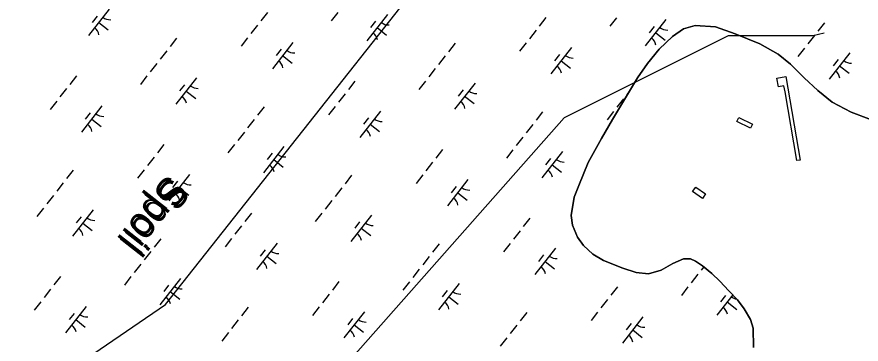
# Model space of a CAD drawing. Extents: x 3896831 to 3918110, y 171006 to 193349.
# Drawn here: x 3911925 to 3913188, y 183055 to 183545 of the extents above; entities that cross this region are included whole.
import ezdxf

# ---------------------------------------------------------------- set-up
doc = ezdxf.new("R2010")
doc.units = 0
for name, color, linetype in [('V-CHAN-DOCK', 7, 'Continuous'), ('V-CHAN-SPOL', 7, 'Continuous'), ('V-TOPO-SHOR', 7, 'Continuous'), ('V-UTIL-LINE', 7, 'Continuous'), ('V-WETL-SWMP', 7, 'Continuous')]:
    doc.layers.add(name, color=color, linetype=linetype)

msp = doc.modelspace()

# ---------------------------------------------------------------- linework, layer by layer
at = {"layer": 'V-CHAN-DOCK'}
for points in [[(3913092.1, 183329.6), (3913074.7, 183432.5), (3913073.1, 183441.5), (3913064.8, 183440.1), (3913062.6, 183453.1), (3913075.9, 183455.3), (3913097.1, 183330.5)], [(3913005.6, 183394.1), (3913025.8, 183384), (3913022.9, 183378.1), (3913002.6, 183388.2)], [(3912941, 183290), (3912955.8, 183279.8), (3912951.1, 183273), (3912936.4, 183283.2)]]:
    msp.add_lwpolyline(points, close=True, dxfattribs=at)
at = {"layer": 'V-TOPO-SHOR'}
msp.add_lwpolyline([(3913027.4, 183050.2), (3913027.2, 183079.1), (3913023, 183091.9), (3913013.7, 183107.9), (3913003.4, 183121.4), (3912990.4, 183134.8), (3912977.1, 183149), (3912964.9, 183160.6), (3912951.3, 183172.2), (3912940.6, 183179.4), (3912933.2, 183182.7), (3912922.6, 183182.6), (3912906.9, 183175.5), (3912889.4, 183165.8), (3912870.4, 183160.1), (3912852.1, 183162.2), (3912832.2, 183168.6), (3912802.8, 183180.4), (3912787.3, 183189.8), (3912773.3, 183202.5), (3912764, 183214.9), (3912756.9, 183232.8), (3912754.6, 183247.4), (3912759.1, 183274.9), (3912765.9, 183292.6), (3912780.3, 183326.8), (3912800.1, 183362.8), (3912816.7, 183391.2), (3912839.1, 183428.4), (3912853.9, 183453.4), (3912868.7, 183474.8), (3912886.5, 183496.2), (3912906.1, 183515.4), (3912922.5, 183526.9), (3912940.4, 183531.8), (3912970.8, 183529.5), (3913000.2, 183519.2), (3913037, 183504.5), (3913064.6, 183489), (3913083, 183473.8), (3913103.4, 183453.4), (3913123.7, 183434.5), (3913145.4, 183417.2), (3913173.8, 183402), (3913200.2, 183392)], dxfattribs=at)
at = {"layer": 'V-UTIL-LINE'}
for points in [[(3905549.4, 173652.6), (3906763.3, 174938.4), (3906949.5, 175133), (3906970.6, 175166.8), (3907325.9, 175860.5), (3907748.9, 176681), (3908142.2, 177273.2), (3908679.4, 178098), (3908869.7, 178381.4), (3908937.4, 178537.8), (3909170, 179117.3), (3909533.8, 179633.3), (3910092.1, 180424.3), (3910333.2, 180766.9), (3910760.4, 181291.4), (3910921.1, 181524), (3911225.6, 181951.2), (3911822, 182788.6), (3911961.6, 182987.4), (3912147.7, 183114.3), (3912722.9, 183841.8), (3913090.9, 184307.1), (3913848, 185258.8), (3914364, 185910.1)], [(3913133.2, 183520.4), (3913116.3, 183516.1), (3912989.4, 183516.1), (3912744.1, 183393.5), (3911902.4, 182441.8), (3910866.1, 181249.1), (3910603.9, 180953), (3910214.7, 180504.6), (3910138.6, 180390.4), (3909757.9, 179819.4), (3909457.6, 179366.9), (3909009.3, 178685.9), (3908785.1, 178351.7), (3908150.7, 177400.1), (3907770, 176816.4), (3907693.9, 176706.4), (3907647.3, 176630.3), (3907300.5, 175936.6), (3907025.6, 175369.8), (3906945.2, 175204.9), (3906416.5, 174650.8), (3905507.1, 173682.2)]]:
    msp.add_lwpolyline(points, dxfattribs=at)
at = {"layer": 'V-WETL-SWMP'}
for p, q in [((3912063.2, 183556), (3912032.3, 183516.7)), ((3912045.4, 183545.8), (3912038, 183536.4)), ((3912300.2, 183551.2), (3912290.4, 183538.6)), ((3912405.7, 183551.1), (3912395.8, 183538.5)), ((3912479.8, 183548.3), (3912449, 183509)), ((3912716.9, 183543.5), (3912707, 183530.9)), ((3912822.3, 183543.4), (3912812.5, 183530.8)), ((3912047.8, 183536.3), (3912061.9, 183525.2)), ((3912285.4, 183532.3), (3912275.6, 183519.7)), ((3912462, 183538.1), (3912454.6, 183528.7)), ((3912464.4, 183528.6), (3912478.6, 183517.5)), ((3912896.5, 183540.6), (3912865.6, 183501.3)), ((3912878.7, 183530.4), (3912871.3, 183521)), ((3912940.4, 183531.8), (3912922.5, 183526.9)), ((3912970.8, 183529.5), (3912940.4, 183531.8)), ((3913000.2, 183519.2), (3912970.8, 183529.5)), ((3913133.5, 183535.8), (3913123.7, 183523.2)), ((3912702.1, 183524.6), (3912692.2, 183512)), ((3912881.1, 183520.9), (3912895.2, 183509.8)), ((3912922.5, 183526.9), (3912906.1, 183515.4)), ((3913037, 183504.5), (3913000.2, 183519.2)), ((3913118.7, 183516.9), (3913108.8, 183504.3)), ((3912164.4, 183512.8), (3912154.5, 183500.2)), ((3912270.6, 183513.4), (3912260.8, 183500.8)), ((3912338.4, 183506.4), (3912307.6, 183467)), ((3912581, 183505.1), (3912571.2, 183492.5)), ((3912687.3, 183505.7), (3912677.4, 183493.1)), ((3912906.1, 183515.4), (3912886.5, 183496.2)), ((3913064.6, 183489), (3913037, 183504.5)), ((3912149.6, 183493.9), (3912139.7, 183481.3)), ((3912320.7, 183496.2), (3912313.2, 183486.7)), ((3912755.1, 183498.7), (3912724.2, 183459.3)), ((3912886.5, 183496.2), (3912868.7, 183474.8)), ((3913103.9, 183498), (3913094, 183485.4)), ((3913171.7, 183491), (3913140.9, 183451.6)), ((3912323, 183486.7), (3912337.2, 183475.6)), ((3912566.2, 183486.2), (3912556.4, 183473.6)), ((3912737.3, 183488.5), (3912729.9, 183479)), ((3912739.7, 183479), (3912753.8, 183467.9)), ((3913083, 183473.8), (3913064.6, 183489)), ((3913153.9, 183480.8), (3913146.5, 183471.3)), ((3912134.8, 183475), (3912124.9, 183462.4)), ((3912551.4, 183467.3), (3912541.6, 183454.7)), ((3912868.7, 183474.8), (3912853.9, 183453.4)), ((3913103.4, 183453.4), (3913083, 183473.8)), ((3913156.3, 183471.3), (3913170.5, 183460.2)), ((3912014.5, 183456.3), (3912004.6, 183443.7)), ((3912120, 183456.2), (3912110.1, 183443.6)), ((3912194.1, 183453.4), (3912163.3, 183414.1)), ((3912853.9, 183453.4), (3912839.1, 183428.4)), ((3913123.7, 183434.5), (3913103.4, 183453.4)), ((3912176.3, 183443.2), (3912168.9, 183433.8)), ((3912431.2, 183448.6), (3912421.3, 183436)), ((3912536.6, 183448.5), (3912526.7, 183435.9)), ((3912610.8, 183445.7), (3912579.9, 183406.4)), ((3911999.7, 183437.4), (3911989.8, 183424.8)), ((3912178.7, 183433.7), (3912192.9, 183422.6)), ((3912416.4, 183429.7), (3912406.5, 183417.1)), ((3912593, 183435.5), (3912585.6, 183426.1)), ((3912839.1, 183428.4), (3912816.7, 183391.2)), ((3912842.5, 183434.1), (3912837.9, 183428.3)), ((3913145.4, 183417.2), (3913123.7, 183434.5)), ((3911984.9, 183418.5), (3911975, 183405.9)), ((3912595.3, 183426), (3912609.5, 183414.9)), ((3912833, 183422), (3912823.1, 183409.4)), ((3913173.8, 183402), (3913145.4, 183417.2)), ((3912052.7, 183411.5), (3912021.9, 183372.1)), ((3912295.3, 183410.2), (3912285.4, 183397.6)), ((3912401.5, 183410.8), (3912391.7, 183398.2)), ((3912469.4, 183403.8), (3912438.5, 183364.4)), ((3912712, 183402.5), (3912702.1, 183389.9)), ((3912818.2, 183403.1), (3912808.3, 183390.5)), ((3912034.9, 183401.3), (3912027.5, 183391.8)), ((3912037.3, 183391.8), (3912051.5, 183380.7)), ((3912280.5, 183391.3), (3912270.6, 183378.7)), ((3912451.6, 183393.6), (3912444.2, 183384.1)), ((3912816.7, 183391.2), (3912800.1, 183362.8)), ((3913200.2, 183392), (3913173.8, 183402)), ((3912453.9, 183384.1), (3912468.1, 183373)), ((3912697.1, 183383.6), (3912687.3, 183371)), ((3912265.7, 183372.4), (3912255.8, 183359.8)), ((3912682.3, 183364.7), (3912672.5, 183352.1)), ((3912145.4, 183353.7), (3912135.6, 183341.1)), ((3912250.9, 183353.5), (3912241, 183341)), ((3912800.1, 183362.8), (3912780.3, 183326.8)), ((3912325, 183350.8), (3912294.2, 183311.5)), ((3912307.2, 183340.6), (3912299.8, 183331.2)), ((3912562.1, 183346), (3912552.2, 183333.4)), ((3912667.5, 183345.8), (3912657.7, 183333.3)), ((3912741.7, 183343.1), (3912710.8, 183303.8)), ((3912130.6, 183334.8), (3912120.8, 183322.2)), ((3912309.6, 183331.1), (3912323.8, 183320)), ((3912547.3, 183327.1), (3912537.4, 183314.5)), ((3912723.9, 183332.9), (3912716.5, 183323.5)), ((3912780.3, 183326.8), (3912765.9, 183292.6)), ((3912009.6, 183315.3), (3911999.7, 183302.7)), ((3912115.8, 183315.9), (3912106, 183303.3)), ((3912726.2, 183323.4), (3912740.4, 183312.3)), ((3912183.6, 183308.9), (3912152.8, 183269.5)), ((3912426.2, 183307.6), (3912416.4, 183295)), ((3912532.5, 183308.2), (3912522.6, 183295.6)), ((3912600.3, 183301.2), (3912569.4, 183261.8)), ((3911994.8, 183296.4), (3911984.9, 183283.8)), ((3912165.8, 183298.7), (3912158.4, 183289.2)), ((3912168.2, 183289.2), (3912182.4, 183278.1)), ((3912411.4, 183288.7), (3912401.6, 183276.1)), ((3912582.5, 183291), (3912575.1, 183281.5)), ((3912765.9, 183292.6), (3912759.1, 183274.9)), ((3911980, 183277.5), (3911970.1, 183264.9)), ((3912584.9, 183281.5), (3912599, 183270.4)), ((3912396.6, 183269.8), (3912386.7, 183257.2)), ((3912759.1, 183274.9), (3912754.6, 183247.4)), ((3911965.2, 183258.6), (3911955.3, 183246)), ((3912039.3, 183255.9), (3912008.5, 183216.5)), ((3912276.3, 183251.1), (3912266.5, 183238.5)), ((3912381.8, 183250.9), (3912371.9, 183238.3)), ((3912021.5, 183245.7), (3912014.1, 183236.3)), ((3912455.9, 183248.2), (3912425.1, 183208.8)), ((3912438.2, 183238), (3912430.8, 183228.6)), ((3912693, 183243.4), (3912683.1, 183230.8)), ((3912754.6, 183247.4), (3912756.9, 183232.8)), ((3912023.9, 183236.2), (3912038, 183225.1)), ((3912261.5, 183232.2), (3912251.7, 183219.6)), ((3912440.5, 183228.5), (3912454.7, 183217.4)), ((3912756.9, 183232.8), (3912764, 183214.9)), ((3912140.5, 183212.7), (3912130.6, 183200.1)), ((3912246.7, 183213.3), (3912236.9, 183200.7)), ((3912678.2, 183224.5), (3912668.3, 183211.9)), ((3912764, 183214.9), (3912773.3, 183202.5)), ((3912314.6, 183206.3), (3912283.7, 183166.9)), ((3912557.1, 183205), (3912547.3, 183192.4)), ((3912663.4, 183205.6), (3912653.5, 183193)), ((3912773.3, 183202.5), (3912787.3, 183189.8)), ((3912125.7, 183193.8), (3912115.8, 183181.2)), ((3912296.8, 183196.1), (3912289.4, 183186.6)), ((3912731.2, 183198.6), (3912700.4, 183159.2)), ((3912713.4, 183188.4), (3912706, 183178.9)), ((3912787.3, 183189.8), (3912802.8, 183180.4)), ((3912110.9, 183174.9), (3912101, 183162.3)), ((3912299.1, 183186.6), (3912313.3, 183175.5)), ((3912542.3, 183186.1), (3912532.5, 183173.5)), ((3912715.8, 183178.9), (3912729.9, 183167.8)), ((3912802.8, 183180.4), (3912832.2, 183168.6)), ((3912889.4, 183165.8), (3912906.9, 183175.5)), ((3912906.9, 183175.5), (3912922.6, 183182.6)), ((3912922.6, 183182.6), (3912933.2, 183182.7)), ((3912933.2, 183182.7), (3912940.6, 183179.4)), ((3912940.6, 183179.4), (3912951.3, 183172.2)), ((3912527.5, 183167.2), (3912517.7, 183154.6)), ((3912832.2, 183168.6), (3912852.1, 183162.2)), ((3912852.1, 183162.2), (3912870.4, 183160.1)), ((3912870.4, 183160.1), (3912889.4, 183165.8)), ((3912953, 183170.7), (3912949.1, 183165.8)), ((3912951.3, 183172.2), (3912964.9, 183160.6)), ((3911990.6, 183156.2), (3911980.8, 183143.6)), ((3912096.1, 183156), (3912086.2, 183143.4)), ((3912170.2, 183153.3), (3912139.4, 183113.9)), ((3912944.2, 183159.5), (3912934.3, 183146.9)), ((3912964.9, 183160.6), (3912977.1, 183149)), ((3911975.8, 183137.3), (3911966, 183124.7)), ((3912152.4, 183143.1), (3912145, 183133.7)), ((3912407.3, 183148.5), (3912397.4, 183135.9)), ((3912512.7, 183148.3), (3912502.9, 183135.7)), ((3912586.9, 183145.6), (3912556, 183106.2)), ((3912823.9, 183140.8), (3912814, 183128.2)), ((3912929.4, 183140.6), (3912919.5, 183128)), ((3912977.1, 183149), (3912990.4, 183134.8)), ((3912154.8, 183133.6), (3912169, 183122.5)), ((3912392.5, 183129.6), (3912382.6, 183117)), ((3912569.1, 183135.4), (3912561.7, 183126)), ((3912571.4, 183125.9), (3912585.6, 183114.8)), ((3912996.3, 183128.7), (3912972.7, 183098.5)), ((3912985.7, 183127.7), (3912978.3, 183118.3)), ((3912990.4, 183134.8), (3913003.4, 183121.4)), ((3911961, 183118.4), (3911951.1, 183105.8)), ((3912809.1, 183121.9), (3912799.2, 183109.3)), ((3912988.1, 183118.2), (3913002.3, 183107.1)), ((3913003.4, 183121.4), (3913013.7, 183107.9)), ((3912028.8, 183111.3), (3911998, 183072)), ((3912011, 183101.1), (3912003.6, 183091.7)), ((3912271.4, 183110.1), (3912261.6, 183097.5)), ((3912377.7, 183110.7), (3912367.8, 183098.1)), ((3912445.5, 183103.6), (3912414.6, 183064.3)), ((3912688.1, 183102.4), (3912678.2, 183089.8)), ((3912794.3, 183103), (3912784.4, 183090.4)), ((3913013.7, 183107.9), (3913023, 183091.9)), ((3912013.4, 183091.7), (3912027.6, 183080.6)), ((3912256.6, 183091.2), (3912246.7, 183078.6)), ((3912427.7, 183093.4), (3912420.3, 183084)), ((3912862.1, 183095.9), (3912831.3, 183056.6)), ((3913023, 183091.9), (3913027.2, 183079.1)), ((3912430.1, 183084), (3912444.2, 183072.9)), ((3912673.3, 183083.5), (3912663.4, 183070.9)), ((3912844.3, 183085.7), (3912836.9, 183076.3)), ((3912846.7, 183076.3), (3912860.9, 183065.2)), ((3913027.2, 183079.1), (3913027.4, 183050.2)), ((3912241.8, 183072.3), (3912231.9, 183059.7)), ((3912658.5, 183064.6), (3912648.6, 183052))]:
    msp.add_line(p, q, dxfattribs=at)
for centre, start, end in [((3912065, 183557.9), 231.1403, 272.6839), ((3912030.9, 183514.5), 11.1403, 52.6839), ((3912481.6, 183550.2), 231.1403, 272.6839), ((3912898.3, 183542.5), 231.1403, 272.6839), ((3912447.6, 183506.8), 11.1403, 52.6839), ((3912864.2, 183499.1), 11.1403, 52.6839), ((3912340.2, 183508.3), 231.1403, 272.6839), ((3912306.2, 183464.8), 11.1403, 52.6839), ((3912756.9, 183500.6), 231.1403, 272.6839), ((3913173.5, 183492.9), 231.1403, 272.6839), ((3912722.8, 183457.1), 11.1403, 52.6839), ((3913139.5, 183449.4), 11.1403, 52.6839), ((3912195.9, 183455.3), 231.1403, 272.6839), ((3912612.6, 183447.6), 231.1403, 272.6839), ((3912161.8, 183411.9), 11.1403, 52.6839), ((3912578.5, 183404.2), 11.1403, 52.6839), ((3912054.5, 183413.4), 231.1403, 272.6839), ((3912471.2, 183405.7), 231.1403, 272.6839), ((3912020.4, 183369.9), 11.1403, 52.6839), ((3912437.1, 183362.2), 11.1403, 52.6839), ((3912326.8, 183352.7), 231.1403, 272.6839), ((3912743.5, 183345), 231.1403, 272.6839), ((3912292.8, 183309.2), 11.1403, 52.6839), ((3912709.4, 183301.5), 11.1403, 52.6839), ((3912185.4, 183310.8), 231.1403, 272.6839), ((3912602.1, 183303.1), 231.1403, 272.6839), ((3912151.4, 183267.3), 11.1403, 52.6839), ((3912568, 183259.6), 11.1403, 52.6839), ((3912041.1, 183257.8), 231.1403, 272.6839), ((3912007, 183214.3), 11.1403, 52.6839), ((3912457.8, 183250.1), 231.1403, 272.6839), ((3912423.7, 183206.6), 11.1403, 52.6839), ((3912316.4, 183208.2), 231.1403, 272.6839), ((3912282.3, 183164.7), 11.1403, 52.6839), ((3912733, 183200.5), 231.1403, 272.6839), ((3912698.9, 183157), 11.1403, 52.6839), ((3912172, 183155.2), 231.1403, 272.6839), ((3912137.9, 183111.7), 11.1403, 52.6839), ((3912588.7, 183147.5), 231.1403, 272.6839), ((3913005.3, 183139.8), 231.1403, 260.241), ((3912554.6, 183104), 11.1403, 52.6839), ((3912030.6, 183113.3), 231.1403, 272.6839), ((3912971.2, 183096.3), 11.1403, 52.6839), ((3912447.3, 183105.6), 231.1403, 272.6839), ((3911996.6, 183069.8), 11.1403, 52.6839), ((3912413.2, 183062.1), 11.1403, 52.6839), ((3912863.9, 183097.9), 231.1403, 272.6839), ((3912829.8, 183054.4), 11.1403, 52.6839)]:
    msp.add_arc(centre, 17.6, start, end, dxfattribs=at)

# ---------------------------------------------------------------- texts
at = {"layer": 'V-CHAN-SPOL'}
msp.add_text('Spoil', height=42, rotation=231.9086, dxfattribs=at).set_placement((3912154.2, 183307))
at = {"layer": 'V-WETL-SWMP'}
msp.add_text('Spoil', height=42, rotation=231.9086, dxfattribs=at).set_placement((3912150.7, 183310.9))

doc.saveas('drawing.dxf')
